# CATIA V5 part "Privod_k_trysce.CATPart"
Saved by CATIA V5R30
Part number: Privod_k_trysce
Definition: EH 4100/37x60/11_1
Nomenclature: EH 4100/37x60/11_1
Source: Unknown
Description: PART--DESC
Bounding box of the stored display mesh (mm): x -108.25 to -71.75, y -18.246 to 18.246, z -24.6 to 55.7
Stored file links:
  E:\Bakalarka\Model\Forma_v7\Privod_k_trysce.CATPart
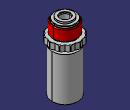
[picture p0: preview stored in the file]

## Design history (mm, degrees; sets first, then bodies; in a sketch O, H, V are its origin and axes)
Body1 "MANIFOLD_SOLID_BREP #3570" (main body)
  Solid1: solid without history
